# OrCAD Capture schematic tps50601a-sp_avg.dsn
size B
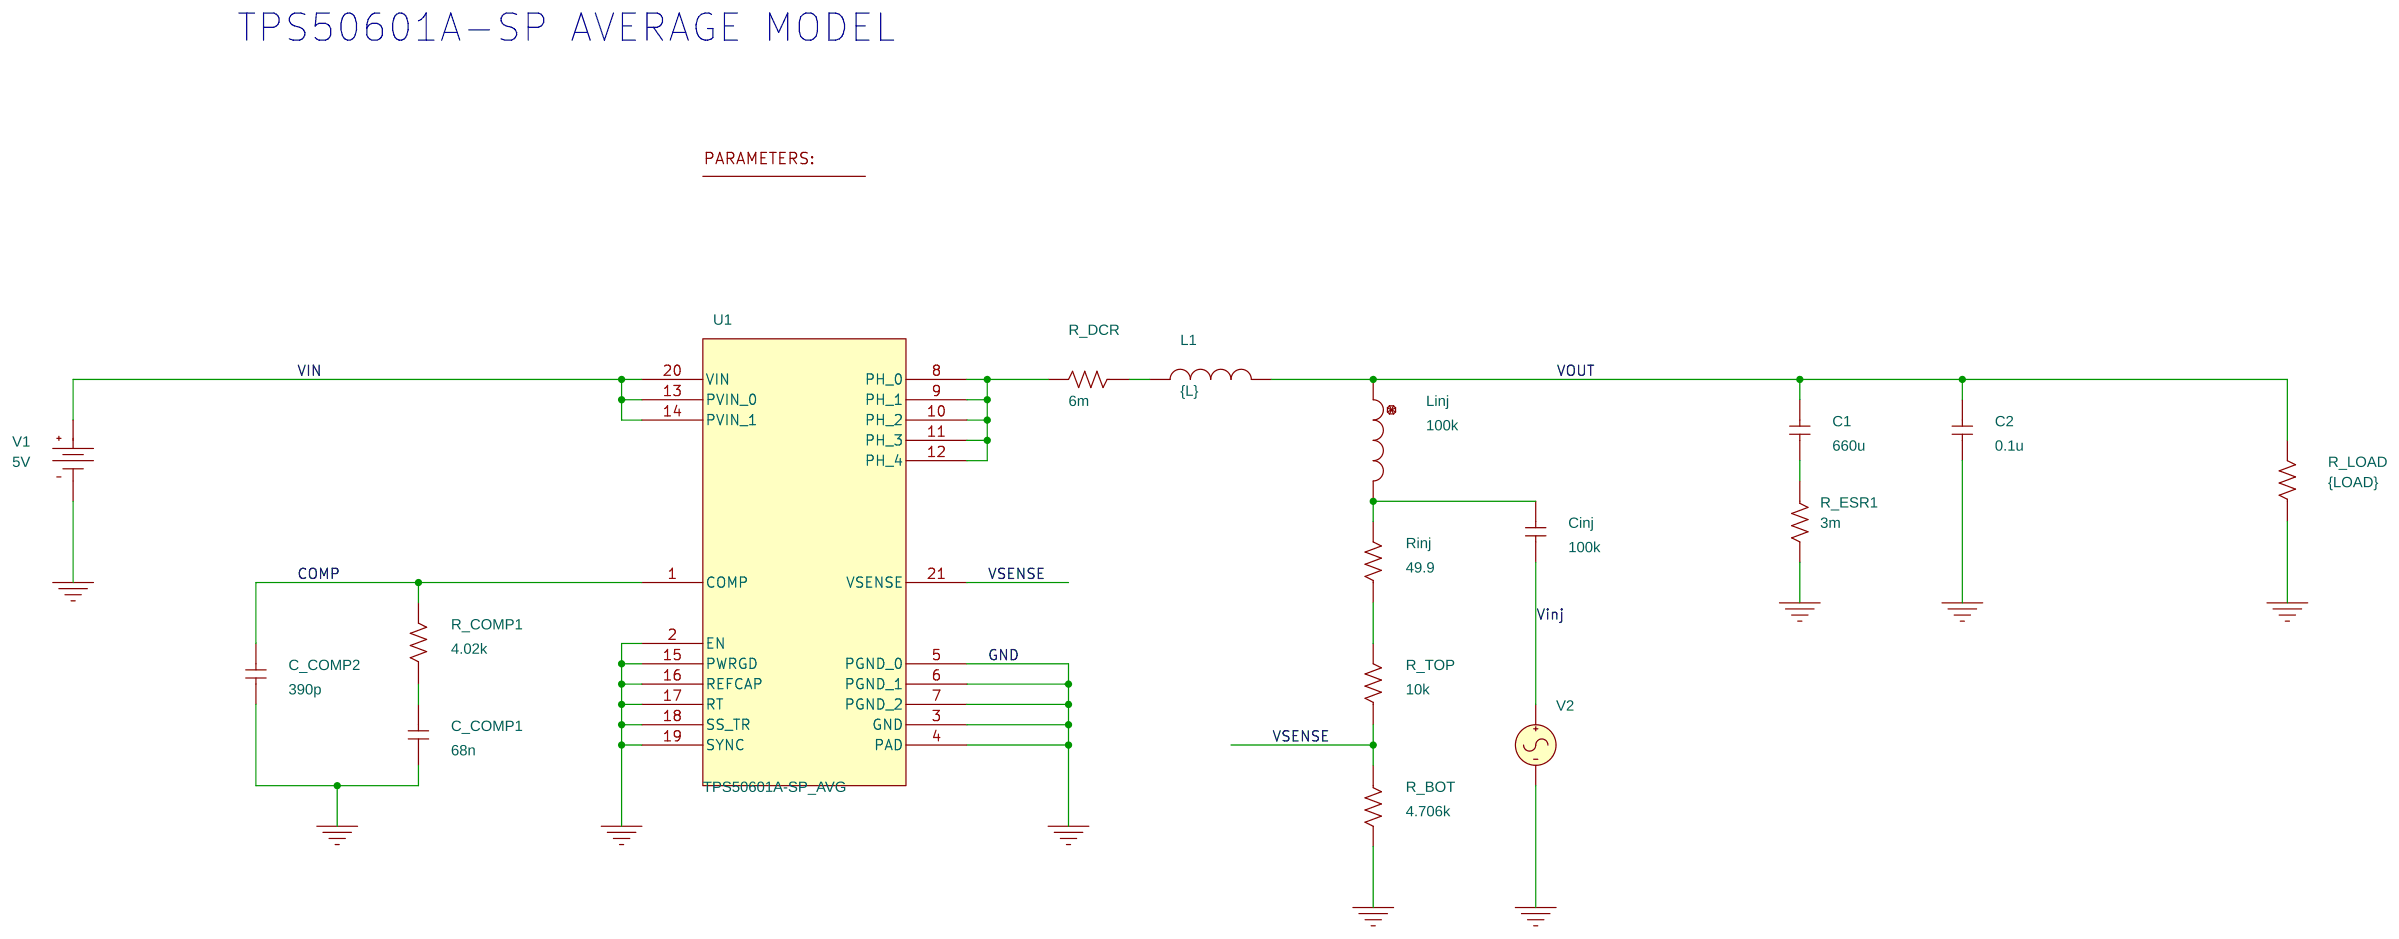
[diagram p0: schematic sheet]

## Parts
1  PARAM
C1  660u  [RAD/CK05]
C2  0.1u  [RAD/CK05]
C_COMP1  68n  [RAD/CK05]
C_COMP2  390p  [RAD/CK05]
Cinj  100k  [RAD/CK05]
L1  {L}  [DISC/.350x.175/LS.200x.100/.034]
Linj  100k  [DISC/.350x.175/LS.200x.100/.034]
R_BOT  4.706k  [AX/RC05]
R_COMP1  4.02k  [AX/RC05]
R_DCR  6m  [AX/RC05]
R_ESR1  3m  [AX/RC05]
R_LOAD  {LOAD}  [AX/RC05]
R_TOP  10k  [AX/RC05]
Rinj  49.9  [AX/RC05]
U1  TPS50601A-SP_AVG
V1  VDC
V2  VAC

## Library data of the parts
1 = PARAM: L: 4.7u
C1 C2 C_COMP1 C_COMP2 Cinj = C
L1 = L_v2
Linj = L
R_BOT R_COMP1 R_DCR R_ESR1 R_LOAD R_TOP Rinj = R
U1 = TPS50601A-SP_AVG_3: FS: 100k; L: 4.7u; PSpiceTemplate: X^@REFDES  %COMP %EN %GND %PAD %PGND_0 %PGND_1 %PGND_2 %PH_0 %PH_1 %PH_2 %PH_3 %PH_4 %PVIN_0 %PVIN_1 %PWRGD %REFCAP %RT %SS_TR %SYNC %VIN %VSENSE @MODEL PARAMS: ?FS|FS=@FS||FS=100k| ?L|L=@L||L=4.7u|
V1 = VDC: DC: 5V
V2 = VAC

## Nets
VIN: U1.13(PVIN_0) U1.14(PVIN_1) U1.20(VIN) V1.0(+)
Vinj: Cinj.2 V2.1(+)
0: C2.2 C_COMP1.2 C_COMP2.2 R_BOT.2 R_ESR1.2 R_LOAD.1 U1.2(EN) U1.3(GND) U1.4(PAD) U1.5(PGND_0) U1.6(PGND_1) U1.7(PGND_2) U1.15(PWRGD) U1.16(REFCAP) U1.17(RT) U1.18(SS_TR) U1.19(SYNC) V1.1(-) V2.2(-)
COMP: C_COMP2.1 R_COMP1.2 U1.1(COMP)
VOUT: C1.1 C2.1 L1.2 Linj.1 R_LOAD.2
VSENSE: R_BOT.1 R_TOP.1 U1.21(VSENSE)
N16764069: L1.1 R_DCR.1
N16764185: C1.2 R_ESR1.1
N16764225: Cinj.1 Linj.2 Rinj.2
N16764381: R_TOP.2 Rinj.1
N16765595: C_COMP1.1 R_COMP1.1
N16767062: R_DCR.2 U1.8(PH_0) U1.9(PH_1) U1.10(PH_2) U1.11(PH_3) U1.12(PH_4)

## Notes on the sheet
- TPS50601A-SP AVERAGE MODEL
